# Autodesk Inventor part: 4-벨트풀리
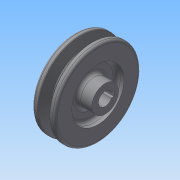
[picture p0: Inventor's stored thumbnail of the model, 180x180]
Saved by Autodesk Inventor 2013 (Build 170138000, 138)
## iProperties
Created: 2015-02
Part Number: 4-벨트풀리
Material: 일반
Document SubType Name: Modeling
Designer: Administrator
Density: 1 g/cm^3
Author: Administrator
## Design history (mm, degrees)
sketch "스케치1"
  geometry: L1 (0, 0)-(25, 0); L2 (0, 11)-(6, 11); L3 (6, 11)-(6, 21.5); L4 (6, 21.5)-(0, 21.5); L5 (0, 21.5)-(0, 35.2); L6 (0, 35.2)-(4.675, 35.2); L7 (4.675, 35.2)-(7.426, 26.2); L8 (7.426, 26.2)-(11.574, 26.2); L9 (11.574, 26.2)-(14.325, 35.2); L10 (14.325, 35.2)-(19, 35.2); L11 (19, 35.2)-(19, 21.5); L12 (19, 21.5)-(13, 21.5); L13 (13, 21.5)-(13, 11); L14 (13, 11)-(25, 11); L15 (25, 11)-(25, 5.5); L16 (25, 5.5)-(0, 5.5); L17 (0, 5.5)-(0, 11); 2 further points
  constraints: 34 end point, 10 parallel, 4 equal length, 4 perpendicular, 3 vertical alignment, 2 collinear, 2 horizontal alignment, 2 point on line, 1 horizontal
  dimensions: "d0" = 25 distance of L1.start L1.end; "d1" = 6 distance of L3.end L4.end; "d2" = 19 distance between parallel lines of L11 L5; "d3" = 8 distance of point (13.5, 32.5) point (5.5, 32.5); "d4" = 34 deg angle of L9 L7; "d5" = 11 diameter of L16 L1; "d6" = 22 diameter of L14 L1; "d7" = 43 diameter of L4 L1; "d8" = 65 diameter of point (5.5, 32.5) L1; "d11" = 2.7 distance from line of point (13.5, 32.5) L10; "d12" = 6.3 distance from line of point (13.5, 32.5) L8
revolve "회전1" sketch "스케치1" stored, may be unused: angle "d13" = 90 deg
sketch "스케치2"
  geometry: L1 (-2, 5.123)-(-2, 7.3); L2 (-2, 7.3)-(2, 7.3); L3 (2, 7.3)-(2, 5.123); A1 r 5.5 centre (0, 0) between (-2, 5.123) and (2, 5.123) reference
  constraints: 6 end point, 2 parallel, 2 point on circle, 1 perpendicular, 1 vertical
  dimensions: "d14" = 4 distance between parallel lines of L3 L1; "d16" = 12.8 dimension on A1 L2
extrude "돌출1" cut sketch "스케치2" stored distance "d17" = 10; taper "d18" = 0 deg
fillet "모깎기1" dims "d19" = 2, "d20" = 0.5, "d21" = 1, "d22" = 3
node "솔리드1"
